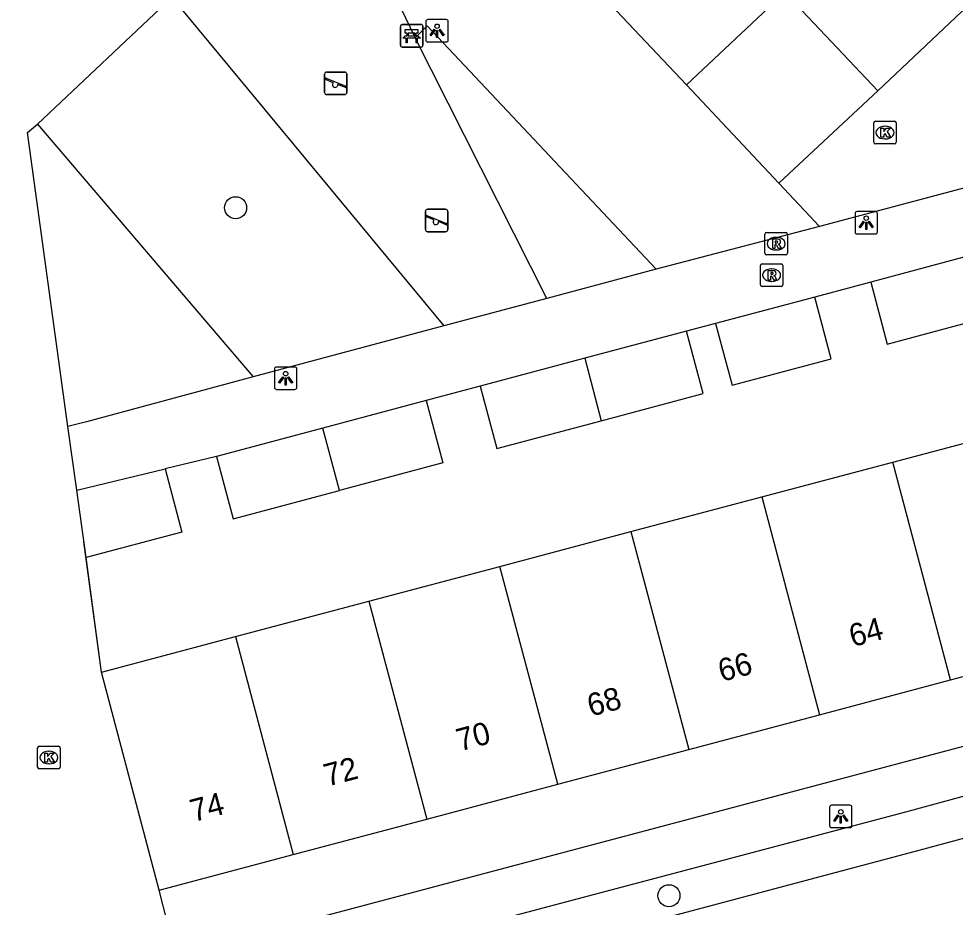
# Model space of a CAD drawing. Extents: x 162542 to 163144, y 380786 to 381511.
# Drawn here: x 162842.94 to 162884.5, y 381162.28 to 381201.72 of the extents above; entities that cross this region are included whole.
import ezdxf

# ---------------------------------------------------------------- set-up
doc = ezdxf.new("R2010")
doc.units = 0
for name, color, linetype in [('IMGEO_Bank', 7, 'Continuous'), ('IMGEO_Boom', 7, 'Continuous'), ('IMGEO_Groenvoorziening', 7, 'Continuous'), ('IMGEO_Kolk', 7, 'Continuous'), ('IMGEO_Lichtpunt', 7, 'Continuous'), ('IMGEO_Muur', 7, 'Continuous'), ('IMGEO_Pand', 7, 'Continuous'), ('IMGEO_Pand_nummerreeks', 7, 'Continuous'), ('IMGEO_Rijbaan_lokaal_open', 7, 'Continuous'), ('IMGEO_Rioolput', 7, 'Continuous'), ('IMGEO_Speelvoorziening', 7, 'Continuous'), ('IMGEO_Voetpad_open', 7, 'Continuous')]:
    doc.layers.add(name, color=color, linetype=linetype)

msp = doc.modelspace()

# ---------------------------------------------------------------- linework, layer by layer
at = {"layer": 'IMGEO_Bank'}
for p, q in [((162859.876, 381200.541), (162859.876, 381201.382)), ((162859.876, 381201.382), (162859.876, 381200.541)), ((162859.951, 381201.466), (162860.792, 381201.466)), ((162860.792, 381201.466), (162859.951, 381201.466)), ((162860.876, 381201.391), (162860.876, 381200.55)), ((162860.876, 381200.55), (162860.876, 381201.391)), ((162860.573, 381200.864), (162860.18, 381200.864)), ((162860.185, 381200.972), (162860.185, 381201.078)), ((162860.229, 381201.078), (162860.229, 381200.972)), ((162860.517, 381201.084), (162860.235, 381201.084)), ((162860.235, 381200.966), (162860.517, 381200.966)), ((162860.523, 381200.972), (162860.523, 381201.078)), ((162860.567, 381201.078), (162860.567, 381200.972)), ((162860.801, 381200.466), (162859.96, 381200.466)), ((162859.96, 381200.466), (162860.801, 381200.466))]:
    msp.add_line(p, q, dxfattribs=at)
for points in [[(162860.179, 381201.084), (162860.093, 381201.084), (162860.093, 381201.245), (162860.656, 381201.245), (162860.656, 381201.084), (162860.573, 381201.084)], [(162860.123, 381200.864), (162859.981, 381200.864), (162860.093, 381200.966), (162860.179, 381200.966)], [(162860.173, 381200.857), (162860.173, 381200.65), (162860.13, 381200.65), (162860.13, 381200.857)], [(162860.573, 381200.966), (162860.656, 381200.966), (162860.768, 381200.864), (162860.629, 381200.864)], [(162860.623, 381200.857), (162860.623, 381200.65), (162860.579, 381200.65), (162860.579, 381200.857)]]:
    msp.add_lwpolyline(points, dxfattribs=at)
for centre, radius, start, end in [((162859.954, 381201.388), 0.0779, 92.4484, 184.2845), ((162859.954, 381201.388), 0.0779, 92.4484, 184.2845), ((162860.798, 381201.388), 0.0779, 2.4484, 94.2845), ((162860.798, 381201.388), 0.0779, 2.4484, 94.2845), ((162860.123, 381200.857), 0.00671, 2.8957, 87.1043), ((162860.18, 381200.857), 0.00671, 92.8957, 177.1043), ((162860.178, 381201.077), 0.00671, 2.8957, 87.1043), ((162860.178, 381200.973), 0.00671, 272.8957, 357.1043), ((162860.235, 381201.077), 0.00671, 92.8957, 177.1043), ((162860.235, 381200.973), 0.00671, 182.8957, 267.1043), ((162860.517, 381201.077), 0.00671, 2.8957, 87.1043), ((162860.517, 381200.973), 0.00671, 272.8957, 357.1043), ((162860.574, 381201.077), 0.00671, 92.8957, 177.1043), ((162860.574, 381200.973), 0.00671, 182.8957, 267.1043), ((162860.572, 381200.857), 0.00671, 2.8957, 87.1043), ((162860.629, 381200.857), 0.00671, 92.8957, 177.1043), ((162859.954, 381200.544), 0.0779, 182.4484, 274.2845), ((162859.954, 381200.544), 0.0779, 182.4484, 274.2845), ((162860.798, 381200.544), 0.0779, 272.4484, 4.2845), ((162860.798, 381200.544), 0.0779, 272.4484, 4.2845)]:
    msp.add_arc(centre, radius, start, end, dxfattribs=at)
at = {"layer": 'IMGEO_Boom'}
for centre in [(162852.566, 381193.333), (162871.792, 381162.796)]:
    msp.add_circle(centre, 0.489, dxfattribs=at)
at = {"layer": 'IMGEO_Groenvoorziening'}
for points in [[(162849.737, 381202.685), (162861.8, 381188.085)], [(162866.381, 381189.299), (162860.535, 381200.874)], [(162843.774, 381197.046), (162853.348, 381185.821)]]:
    msp.add_lwpolyline(points, dxfattribs=at)
at = {"layer": 'IMGEO_Kolk'}
for p, q in [((162880.88, 381196.244), (162880.88, 381197.096)), ((162880.955, 381197.17), (162881.807, 381197.17)), ((162881.881, 381197.096), (162881.881, 381196.244)), ((162881.368, 381196.95), (162881.393, 381196.95)), ((162881.391, 381196.39), (162881.366, 381196.39)), ((162881.807, 381196.17), (162880.955, 381196.17)), ((162843.781, 381168.503), (162843.781, 381169.355)), ((162843.856, 381169.429), (162844.708, 381169.429)), ((162844.269, 381169.209), (162844.294, 381169.209)), ((162844.782, 381169.355), (162844.782, 381168.503)), ((162844.708, 381168.429), (162843.856, 381168.429)), ((162844.292, 381168.649), (162844.267, 381168.649))]:
    msp.add_line(p, q, dxfattribs=at)
for points in [[(162880.88, 381196.244), (162880.88, 381197.096)], [(162880.955, 381197.17), (162881.807, 381197.17)], [(162881.881, 381197.096), (162881.881, 381196.244)], [(162881.201, 381196.87), (162881.324, 381196.87), (162881.324, 381196.719), (162881.454, 381196.87), (162881.618, 381196.87), (162881.472, 381196.719), (162881.625, 381196.47), (162881.473, 381196.47), (162881.388, 381196.634), (162881.324, 381196.567), (162881.324, 381196.47), (162881.201, 381196.47), (162881.201, 381196.87)], [(162881.807, 381196.17), (162880.955, 381196.17)], [(162843.781, 381168.503), (162843.781, 381169.355)], [(162843.856, 381169.429), (162844.708, 381169.429)], [(162844.782, 381169.355), (162844.782, 381168.503)], [(162844.102, 381169.129), (162844.225, 381169.129), (162844.225, 381168.978), (162844.355, 381169.129), (162844.519, 381169.129), (162844.373, 381168.978), (162844.526, 381168.729), (162844.374, 381168.729), (162844.289, 381168.893), (162844.225, 381168.826), (162844.225, 381168.729), (162844.102, 381168.729), (162844.102, 381169.129)], [(162844.708, 381168.429), (162843.856, 381168.429)]]:
    msp.add_lwpolyline(points, dxfattribs=at)
for centre, start, end in [((162880.957, 381197.094), 91.552, 178.448), ((162880.957, 381197.094), 91.552, 178.448), ((162881.805, 381197.094), 1.552, 88.448), ((162881.805, 381197.094), 1.552, 88.448), ((162880.957, 381196.246), 181.552, 268.448), ((162880.957, 381196.246), 181.552, 268.448), ((162881.805, 381196.246), 271.552, 358.448), ((162881.805, 381196.246), 271.552, 358.448), ((162843.858, 381169.353), 91.552, 178.448), ((162843.858, 381169.353), 91.552, 178.448), ((162844.706, 381169.353), 1.552, 88.448), ((162844.706, 381169.353), 1.552, 88.448), ((162843.858, 381168.505), 181.552, 268.448), ((162843.858, 381168.505), 181.552, 268.448), ((162844.706, 381168.505), 271.552, 358.448), ((162844.706, 381168.505), 271.552, 358.448)]:
    msp.add_arc(centre, 0.0765, start, end, dxfattribs=at)
for centre, major_axis, ratio, start_param, end_param in [((162881.367, 381196.67), (-0.387, 0.002), 0.722429, 4.712389, 7.853982), ((162881.392, 381196.67), (-0.39, 0.002), 0.717154, 1.570796, 4.712389), ((162844.268, 381168.929), (-0.387, 0.002), 0.722429, 4.712389, 7.853982), ((162844.293, 381168.929), (-0.39, 0.002), 0.717154, 1.570796, 4.712389)]:
    msp.add_ellipse(centre, major_axis=major_axis, ratio=ratio, start_param=start_param, end_param=end_param, dxfattribs=at)
at = {"layer": 'IMGEO_Lichtpunt'}
for p, q in [((162861.909, 381201.687), (162861.101, 381201.687)), ((162861.909, 381201.687), (162861.101, 381201.687)), ((162861.007, 381201.592), (162861.007, 381200.785)), ((162861.007, 381201.592), (162861.007, 381200.785)), ((162862.003, 381200.785), (162862.003, 381201.592)), ((162862.003, 381200.785), (162862.003, 381201.592)), ((162861.101, 381200.691), (162861.909, 381200.691)), ((162861.101, 381200.691), (162861.909, 381200.691)), ((162880.05, 381193.071), (162880.05, 381192.264)), ((162880.05, 381193.071), (162880.05, 381192.264)), ((162880.952, 381193.166), (162880.144, 381193.166)), ((162880.952, 381193.166), (162880.144, 381193.166)), ((162881.046, 381192.264), (162881.046, 381193.071)), ((162881.046, 381192.264), (162881.046, 381193.071)), ((162880.144, 381192.17), (162880.952, 381192.17)), ((162880.144, 381192.17), (162880.952, 381192.17)), ((162855.19, 381186.264), (162854.382, 381186.264)), ((162855.19, 381186.264), (162854.382, 381186.264)), ((162854.288, 381186.169), (162854.288, 381185.362)), ((162854.288, 381186.169), (162854.288, 381185.362)), ((162855.284, 381185.362), (162855.284, 381186.169)), ((162855.284, 381185.362), (162855.284, 381186.169)), ((162854.382, 381185.268), (162855.19, 381185.268)), ((162854.382, 381185.268), (162855.19, 381185.268)), ((162878.919, 381166.717), (162878.919, 381165.91)), ((162878.919, 381166.717), (162878.919, 381165.91)), ((162879.821, 381166.812), (162879.013, 381166.812)), ((162879.821, 381166.812), (162879.013, 381166.812)), ((162879.915, 381165.91), (162879.915, 381166.717)), ((162879.915, 381165.91), (162879.915, 381166.717)), ((162879.013, 381165.816), (162879.821, 381165.816)), ((162879.013, 381165.816), (162879.821, 381165.816))]:
    msp.add_line(p, q, dxfattribs=at)
for points in [[(162861.381, 381201.256), (162861.42, 381201.228), (162861.232, 381200.966), (162861.194, 381200.993), (162861.381, 381201.256)], [(162861.483, 381201.208), (162861.53, 381201.208), (162861.53, 381200.886), (162861.483, 381200.886), (162861.483, 381201.208)], [(162861.593, 381201.228), (162861.631, 381201.255), (162861.818, 381200.993), (162861.779, 381200.965), (162861.593, 381201.228)], [(162880.424, 381192.735), (162880.463, 381192.707), (162880.275, 381192.445), (162880.237, 381192.472), (162880.424, 381192.735)], [(162880.526, 381192.687), (162880.573, 381192.687), (162880.573, 381192.365), (162880.526, 381192.365), (162880.526, 381192.687)], [(162880.636, 381192.707), (162880.674, 381192.734), (162880.861, 381192.472), (162880.822, 381192.444), (162880.636, 381192.707)], [(162854.662, 381185.833), (162854.701, 381185.805), (162854.513, 381185.543), (162854.475, 381185.57), (162854.662, 381185.833)], [(162854.874, 381185.805), (162854.912, 381185.832), (162855.099, 381185.57), (162855.06, 381185.542), (162854.874, 381185.805)], [(162854.764, 381185.785), (162854.811, 381185.785), (162854.811, 381185.463), (162854.764, 381185.463), (162854.764, 381185.785)], [(162879.293, 381166.381), (162879.332, 381166.353), (162879.144, 381166.091), (162879.106, 381166.118), (162879.293, 381166.381)], [(162879.395, 381166.333), (162879.442, 381166.333), (162879.442, 381166.011), (162879.395, 381166.011), (162879.395, 381166.333)], [(162879.505, 381166.353), (162879.543, 381166.38), (162879.73, 381166.118), (162879.691, 381166.09), (162879.505, 381166.353)]]:
    msp.add_lwpolyline(points, dxfattribs=at)
for centre in [(162861.506, 381201.39), (162880.549, 381192.869), (162854.787, 381185.967), (162879.418, 381166.515)]:
    msp.add_circle(centre, 0.0994, dxfattribs=at)
for centre, start, end in [((162861.101, 381201.592), 90, 180), ((162861.101, 381201.592), 90, 180), ((162861.909, 381201.592), 0, 90), ((162861.909, 381201.592), 0, 90), ((162861.101, 381200.785), 180, 270), ((162861.101, 381200.785), 180, 270), ((162861.909, 381200.785), 270, 0), ((162861.909, 381200.785), 270, 360), ((162880.144, 381193.071), 90, 180), ((162880.144, 381193.071), 90, 180), ((162880.952, 381193.071), 0, 90), ((162880.952, 381193.071), 0, 90), ((162880.144, 381192.264), 180, 270), ((162880.144, 381192.264), 180, 270), ((162880.952, 381192.264), 270, 0), ((162880.952, 381192.264), 270, 360), ((162854.382, 381186.169), 90, 180), ((162854.382, 381186.169), 90, 180), ((162855.19, 381186.169), 0, 90), ((162855.19, 381186.169), 0, 90), ((162854.382, 381185.362), 180, 270), ((162854.382, 381185.362), 180, 270), ((162855.19, 381185.362), 270, 0), ((162855.19, 381185.362), 270, 360), ((162879.013, 381166.717), 90, 180), ((162879.013, 381166.717), 90, 180), ((162879.821, 381166.717), 0, 90), ((162879.821, 381166.717), 0, 90), ((162879.013, 381165.91), 180, 270), ((162879.013, 381165.91), 180, 270), ((162879.821, 381165.91), 270, 0), ((162879.821, 381165.91), 270, 360)]:
    msp.add_arc(centre, 0.0946, start, end, dxfattribs=at)
at = {"layer": 'IMGEO_Muur'}
msp.add_lwpolyline([(162846.614, 381172.717), (162845.835, 381178.51)], dxfattribs=at)
at = {"layer": 'IMGEO_Pand'}
for points in [[(162864.025, 381207.85), (162872.577, 381198.788)], [(162881.058, 381198.523), (162890.12, 381207.083)], [(162872.577, 381198.788), (162876.942, 381202.907), (162881.058, 381198.523)], [(162885.484, 381191.296), (162880.747, 381190.032)], [(162880.747, 381190.032), (162881.48, 381187.283), (162886.214, 381188.545), (162885.484, 381191.296)], [(162878.26, 381189.369), (162873.866, 381188.198)], [(162873.866, 381188.198), (162874.321, 381186.487), (162874.594, 381185.457), (162878.989, 381186.624), (162878.26, 381189.369)], [(162872.573, 381187.853), (162868.056, 381186.649)], [(162868.793, 381183.881), (162873.308, 381185.085), (162872.573, 381187.853)], [(162868.056, 381186.649), (162863.413, 381185.411)], [(162868.056, 381186.649), (162868.793, 381183.881)], [(162863.413, 381185.411), (162864.151, 381182.644), (162868.793, 381183.881)], [(162861.025, 381184.774), (162856.439, 381183.551)], [(162861.025, 381184.774), (162861.763, 381182.006), (162857.174, 381180.783)], [(162856.439, 381183.551), (162851.718, 381182.292)], [(162857.174, 381180.783), (162856.439, 381183.551)], [(162881.722, 381182.041), (162887.533, 381183.585)], [(162851.718, 381182.292), (162852.451, 381179.525), (162857.174, 381180.783)], [(162845.527, 381180.8), (162849.437, 381181.742)], [(162849.437, 381181.742), (162850.181, 381178.934), (162845.93, 381177.801)], [(162875.911, 381180.498), (162881.722, 381182.041)], [(162884.29, 381172.375), (162881.722, 381182.041)], [(162845.93, 381177.801), (162845.527, 381180.8)], [(162870.101, 381178.955), (162875.911, 381180.498)], [(162875.911, 381180.498), (162878.48, 381170.831)], [(162864.29, 381177.412), (162870.101, 381178.955)], [(162870.101, 381178.955), (162872.669, 381169.287)], [(162858.48, 381175.869), (162864.29, 381177.412)], [(162866.859, 381167.744), (162864.29, 381177.412)], [(162852.558, 381174.296), (162858.48, 381175.869)], [(162858.48, 381175.869), (162861.048, 381166.2)], [(162846.614, 381172.717), (162852.558, 381174.296)], [(162852.558, 381174.296), (162855.117, 381164.624)], [(162884.29, 381172.375), (162890.101, 381173.918)], [(162849.174, 381163.045), (162846.614, 381172.717)], [(162878.48, 381170.831), (162884.29, 381172.375)], [(162872.669, 381169.287), (162878.48, 381170.831)], [(162866.859, 381167.744), (162872.669, 381169.287)], [(162861.048, 381166.2), (162866.859, 381167.744)], [(162855.117, 381164.624), (162861.048, 381166.2)], [(162849.174, 381163.045), (162855.117, 381164.624)]]:
    msp.add_lwpolyline(points, dxfattribs=at)
at = {"layer": 'IMGEO_Rijbaan_lokaal_open'}
msp.add_lwpolyline([(162901.876, 381169.92), (162882.877, 381164.808), (162796.063, 381141.696)], dxfattribs=at)
at = {"layer": 'IMGEO_Rioolput'}
for p, q in [((162876.051, 381191.312), (162876.051, 381192.164)), ((162876.126, 381192.238), (162876.978, 381192.238)), ((162877.052, 381192.164), (162877.052, 381191.312)), ((162876.539, 381192.018), (162876.564, 381192.018)), ((162876.978, 381191.238), (162876.126, 381191.238)), ((162876.562, 381191.458), (162876.537, 381191.458)), ((162875.924, 381190.84), (162876.776, 381190.84)), ((162875.849, 381189.914), (162875.849, 381190.766)), ((162876.337, 381190.62), (162876.362, 381190.62)), ((162876.85, 381190.766), (162876.85, 381189.914)), ((162876.36, 381190.06), (162876.335, 381190.06)), ((162876.776, 381189.84), (162875.924, 381189.84))]:
    msp.add_line(p, q, dxfattribs=at)
for points in [[(162876.051, 381191.312), (162876.051, 381192.164)], [(162876.126, 381192.238), (162876.978, 381192.238)], [(162877.052, 381192.164), (162877.052, 381191.312)], [(162876.64, 381191.936), (162876.388, 381191.938), (162876.388, 381191.538)], [(162876.388, 381191.538), (162876.512, 381191.538), (162876.512, 381191.7), (162876.523, 381191.7)], [(162876.566, 381191.857), (162876.512, 381191.857), (162876.512, 381191.776)], [(162876.512, 381191.776), (162876.564, 381191.776)], [(162876.57, 381191.671), (162876.641, 381191.538), (162876.781, 381191.538), (162876.716, 381191.664)], [(162876.978, 381191.238), (162876.126, 381191.238)], [(162875.924, 381190.84), (162876.776, 381190.84)], [(162875.849, 381189.914), (162875.849, 381190.766)], [(162876.438, 381190.538), (162876.186, 381190.54), (162876.186, 381190.14)], [(162876.364, 381190.459), (162876.31, 381190.459), (162876.31, 381190.378)], [(162876.85, 381190.766), (162876.85, 381189.914)], [(162876.186, 381190.14), (162876.31, 381190.14), (162876.31, 381190.302), (162876.321, 381190.302)], [(162876.31, 381190.378), (162876.362, 381190.378)], [(162876.368, 381190.273), (162876.439, 381190.14), (162876.579, 381190.14), (162876.514, 381190.266)], [(162876.776, 381189.84), (162875.924, 381189.84)]]:
    msp.add_lwpolyline(points, dxfattribs=at)
for centre, radius, start, end in [((162876.128, 381192.162), 0.0765, 91.552, 178.448), ((162876.128, 381192.162), 0.0765, 91.552, 178.448), ((162876.976, 381192.162), 0.0765, 1.552, 88.448), ((162876.976, 381192.162), 0.0765, 1.552, 88.448), ((162876.522, 381191.647), 0.0533, 26.0293, 88.6989), ((162876.548, 381191.965), 0.19, 274.7715, 282.9687), ((162876.572, 381191.761), 0.0964, 77.0061, 93.1865), ((162876.586, 381191.818), 0.0378, 276.6634, 79.6772), ((162876.639, 381191.826), 0.109, 350.3612, 89.416), ((162876.637, 381191.826), 0.112, 277.5842, 350.9817), ((162876.621, 381191.611), 0.108, 29.5134, 73.7905), ((162876.128, 381191.314), 0.0765, 181.552, 268.448), ((162876.128, 381191.314), 0.0765, 181.552, 268.448), ((162876.976, 381191.314), 0.0765, 271.552, 358.448), ((162876.976, 381191.314), 0.0765, 271.552, 358.448), ((162875.926, 381190.764), 0.0765, 91.552, 178.448), ((162875.926, 381190.764), 0.0765, 91.552, 178.448), ((162876.774, 381190.764), 0.0765, 1.552, 88.448), ((162876.774, 381190.764), 0.0765, 1.552, 88.448), ((162876.37, 381190.363), 0.0964, 77.0061, 93.1865), ((162876.384, 381190.42), 0.0378, 276.6634, 79.6772), ((162876.437, 381190.428), 0.109, 350.3612, 89.416), ((162876.435, 381190.428), 0.112, 277.5842, 350.9817), ((162876.32, 381190.249), 0.0533, 26.0293, 88.6989), ((162876.346, 381190.567), 0.19, 274.7715, 282.9687), ((162876.419, 381190.213), 0.108, 29.5134, 73.7905), ((162875.926, 381189.916), 0.0765, 181.552, 268.448), ((162875.926, 381189.916), 0.0765, 181.552, 268.448), ((162876.774, 381189.916), 0.0765, 271.552, 358.448), ((162876.774, 381189.916), 0.0765, 271.552, 358.448)]:
    msp.add_arc(centre, radius, start, end, dxfattribs=at)
for centre, major_axis, ratio, start_param, end_param in [((162876.538, 381191.738), (-0.387, 0.002), 0.722429, 4.712389, 7.853982), ((162876.563, 381191.738), (-0.39, 0.002), 0.717154, 1.570796, 4.712389), ((162876.336, 381190.34), (-0.387, 0.002), 0.722429, 4.712389, 7.853982), ((162876.361, 381190.34), (-0.39, 0.002), 0.717154, 1.570796, 4.712389)]:
    msp.add_ellipse(centre, major_axis=major_axis, ratio=ratio, start_param=start_param, end_param=end_param, dxfattribs=at)
at = {"layer": 'IMGEO_Speelvoorziening'}
for p, q in [((162856.518, 381198.456), (162856.518, 381199.256)), ((162856.518, 381199.256), (162856.518, 381198.456)), ((162856.618, 381199.356), (162857.408, 381199.356)), ((162857.408, 381199.356), (162856.618, 381199.356)), ((162857.508, 381199.256), (162857.508, 381198.456)), ((162857.508, 381198.456), (162857.508, 381199.256)), ((162856.901, 381198.884), (162856.562, 381199.021)), ((162856.587, 381199.081), (162857.463, 381198.728)), ((162857.439, 381198.668), (162857.099, 381198.805)), ((162857.408, 381198.356), (162856.618, 381198.356)), ((162856.618, 381198.356), (162857.408, 381198.356)), ((162860.986, 381192.368), (162860.986, 381193.168)), ((162860.986, 381193.168), (162860.986, 381192.368)), ((162861.369, 381192.796), (162861.03, 381192.933)), ((162861.055, 381192.993), (162861.931, 381192.64)), ((162861.086, 381193.268), (162861.876, 381193.268)), ((162861.876, 381193.268), (162861.086, 381193.268)), ((162861.976, 381193.168), (162861.976, 381192.368)), ((162861.976, 381192.368), (162861.976, 381193.168)), ((162861.907, 381192.58), (162861.567, 381192.717)), ((162861.876, 381192.268), (162861.086, 381192.268)), ((162861.086, 381192.268), (162861.876, 381192.268))]:
    msp.add_line(p, q, dxfattribs=at)
for centre, radius, start, end in [((162856.618, 381199.256), 0.1, 90, 180), ((162856.618, 381199.256), 0.1, 90, 180), ((162857.408, 381199.256), 0.1, 0, 90), ((162857.408, 381199.256), 0.1, 360, 90), ((162856.575, 381199.051), 0.0327, 68.078, 248.078), ((162856.98, 381198.794), 0.12, 130.9928, 5.1632), ((162857.451, 381198.698), 0.0327, 248.078, 68.078), ((162856.618, 381198.456), 0.1, 180, 270), ((162856.618, 381198.456), 0.1, 180, 270), ((162857.408, 381198.456), 0.1, 270, 0), ((162857.408, 381198.456), 0.1, 270, 0), ((162861.086, 381193.168), 0.1, 90, 180), ((162861.086, 381193.168), 0.1, 90, 180), ((162861.043, 381192.963), 0.0327, 68.078, 248.078), ((162861.876, 381193.168), 0.1, 0, 90), ((162861.876, 381193.168), 0.1, 360, 90), ((162861.448, 381192.706), 0.12, 130.9928, 5.1632), ((162861.919, 381192.61), 0.0327, 248.078, 68.078), ((162861.086, 381192.368), 0.1, 180, 270), ((162861.086, 381192.368), 0.1, 180, 270), ((162861.876, 381192.368), 0.1, 270, 0), ((162861.876, 381192.368), 0.1, 270, 0)]:
    msp.add_arc(centre, radius, start, end, dxfattribs=at)
at = {"layer": 'IMGEO_Voetpad_open'}
for points in [[(162854.551, 381207.255), (162857.703, 381206.728), (162860.535, 381200.874)], [(162843.774, 381197.046), (162849.737, 381202.685)], [(162860.535, 381200.874), (162861.066, 381201.401), (162871.229, 381190.605)], [(162905.326, 381199.652), (162878.474, 381192.504)], [(162872.577, 381198.788), (162876.676, 381194.423)], [(162876.676, 381194.423), (162881.058, 381198.523)], [(162845.122, 381183.618), (162843.333, 381196.675), (162843.774, 381197.046)], [(162878.474, 381192.504), (162876.676, 381194.423)], [(162878.474, 381192.504), (162871.229, 381190.605)], [(162871.229, 381190.605), (162866.381, 381189.299)], [(162880.747, 381190.032), (162878.26, 381189.369)], [(162866.381, 381189.299), (162861.8, 381188.085)], [(162861.8, 381188.085), (162853.348, 381185.821)], [(162873.866, 381188.198), (162872.573, 381187.853)], [(162853.348, 381185.821), (162845.945, 381183.837), (162845.122, 381183.618)], [(162863.413, 381185.411), (162861.025, 381184.774)], [(162845.527, 381180.8), (162845.122, 381183.618)], [(162925.455, 381182.694), (162921.793, 381179.222), (162849.909, 381160.144)], [(162851.718, 381182.292), (162849.437, 381181.742)], [(162846.614, 381172.717), (162845.93, 381177.801)], [(162850.91, 381158.201), (162882.303, 381166.521), (162903.648, 381172.331)], [(162849.909, 381160.144), (162849.174, 381163.045)]]:
    msp.add_lwpolyline(points, dxfattribs=at)

# ---------------------------------------------------------------- texts
at = {"layer": 'IMGEO_Pand_nummerreeks'}
for s, p in [('64', (162879.942, 381173.827)), ('66', (162874.132, 381172.283)), ('68', (162868.324, 381170.74)), ('70', (162862.514, 381169.197)), ('72', (162856.634, 381167.634)), ('74', (162850.702, 381166.059))]:
    msp.add_text(s, height=1, rotation=14.8786, dxfattribs=at).set_placement(p)

doc.saveas('drawing.dxf')
